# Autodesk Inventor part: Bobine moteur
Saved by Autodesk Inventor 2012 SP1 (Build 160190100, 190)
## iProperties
Created: 2014-12
Part Number: Bobine moteur
Material: Default
Document SubType Name: Modeling
Designer: Bruno
Density: 1 g/cm^3
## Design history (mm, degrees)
node "Bobine moteur1"
node "Bobine moteur"
node "Base1"
